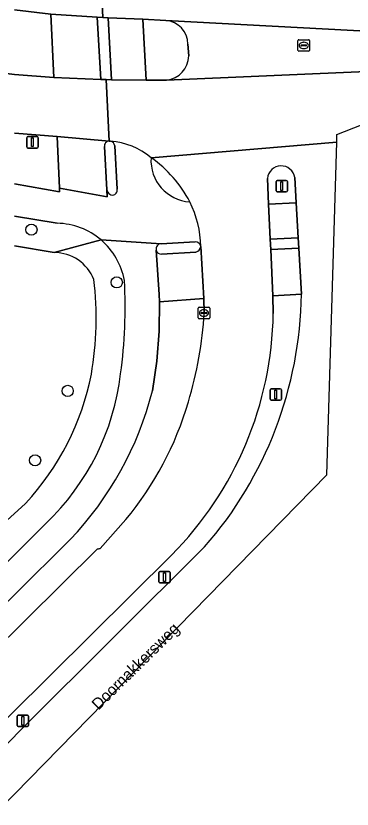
# Model space of a CAD drawing. Extents: x 162989 to 165008, y 383432 to 384338.
# Drawn here: x 164500.1 to 164529.5, y 383437.3 to 383506.5 of the extents above; entities that cross this region are included whole.
import ezdxf

# ---------------------------------------------------------------- set-up
doc = ezdxf.new("R2010")
doc.units = 0
for name, color, linetype in [('IMGEO_Boom', 7, 'Continuous'), ('IMGEO_Fietspad_open', 7, 'Continuous'), ('IMGEO_Groenvoorziening', 7, 'Continuous'), ('IMGEO_Kolk', 7, 'Continuous'), ('IMGEO_Lichtmast', 7, 'Continuous'), ('IMGEO_Openbare_ruimte_label', 7, 'Continuous'), ('IMGEO_Rijbaan_lokaal_open', 7, 'Continuous'), ('IMGEO_Rioolput', 7, 'Continuous'), ('IMGEO_Verkeerseiland_open', 7, 'Continuous'), ('IMGEO_Voetpad_open', 7, 'Continuous')]:
    doc.layers.add(name, color=color, linetype=linetype)

msp = doc.modelspace()

# ---------------------------------------------------------------- linework, layer by layer
at = {"layer": 'IMGEO_Boom'}
for centre in [(164501.471, 383487.838), (164508.917, 383483.242), (164504.637, 383473.78), (164501.79, 383467.725)]:
    msp.add_circle(centre, 0.489, dxfattribs=at)
at = {"layer": 'IMGEO_Fietspad_open'}
for points in [[(164508.175, 383506.302), (164508.462, 383500.91), (164511.494, 383500.886), (164511.191, 383506.197)], [(164522.169, 383490.055), (164522.306, 383487.021), (164524.749, 383487.13), (164524.575, 383490.167)]]:
    msp.add_lwpolyline(points, close=True, dxfattribs=at)
for points in [[(164508.736, 383495.164), (164508.961, 383491.369)], [(164508.065, 383491.313), (164508.078, 383490.705), (164503.931, 383491.447), (164503.925, 383491.144), (164500, 383491.824)], [(164500, 383489.02), (164503.729, 383488.399)], [(164512.789, 383486.617), (164507.545, 383486.942)], [(164507.545, 383486.942), (164512.789, 383486.617), (164515.771, 383486.781)], [(164512.027, 383473.783), (164512.425, 383476.376), (164512.63, 383478.992), (164512.642, 383481.539), (164512.604, 383482.199), (164512.352, 383486.065)], [(164502.742, 383462.221), (164500, 383459.479), (164492.313, 383451.968), (164487.834, 383447.544), (164489.625, 383445.869), (164491.555, 383447.775), (164494.035, 383450.225), (164500, 383456.001), (164504.839, 383460.807)]]:
    msp.add_lwpolyline(points, dxfattribs=at)
for centre, radius, start, end in [((164507.881, 383489.285), 6.288, 50.18021, 85.4974), ((164508.288, 383495.112), 0.451, 6.65512, 78.92211), ((164515.54, 383493.888), 3.639, 176.427, 266.03104), ((164508.567, 383491.361), 0.504, 185.47352, 270.70178), ((164508.522, 383491.299), 0.445, 276.64521, 9.04418), ((164507.422, 383486.258), 8.824, 0.75448, 26.95674), ((164503.585, 383482.297), 6.104, 49.55365, 88.6513), ((164503.587, 383482.299), 6.101, 10.44461, 49.55325), ((164512.824, 383486.141), 0.478, 94.14439, 189.12064), ((164515.78, 383486.311), 0.47, 7.6989, 91.11839), ((164466.759, 383481.075), 42.891, 352.23468, 3.11369), ((164487.794, 383477.833), 21.614, 313.75529, 353.21644), ((164483.733, 383480.977), 29.194, 316.29812, 345.73373)]:
    msp.add_arc(centre, radius, start, end, dxfattribs=at)
at = {"layer": 'IMGEO_Groenvoorziening'}
for points in [[(164500, 383491.824), (164503.925, 383491.144), (164503.931, 383491.447), (164503.705, 383495.962), (164500, 383496.248)], [(164477.652, 383492.496), (164481.464, 383487.201), (164486.535, 383481.42), (164488.702, 383478.589), (164492.282, 383473.121), (164497.415, 383463.608), (164498.327, 383461.598), (164500.966, 383463.964)], [(164503.462, 383485.847), (164500, 383486.434)], [(164516.552, 383480.597), (164516.501, 383481.85), (164512.642, 383481.539), (164512.63, 383478.992), (164512.425, 383476.376), (164512.027, 383473.783)], [(164504.839, 383460.807), (164500, 383456.001), (164494.035, 383450.225), (164491.555, 383447.775), (164493.231, 383446.235), (164493.418, 383446.419), (164494.784, 383447.72), (164507.212, 383459.964), (164507.457, 383460.024), (164509.711, 383462.56)]]:
    msp.add_lwpolyline(points, dxfattribs=at)
for centre, radius, start, end in [((164503.432, 383482.083), 3.764, 22.02729, 89.54402), ((164478.075, 383480.132), 29.041, 350.28617, 6.64972), ((164482.063, 383482.734), 34.555, 343.31323, 356.45424), ((164483.929, 383479.727), 23.21, 317.22478, 348.83444), ((164483.733, 383480.977), 29.194, 316.29812, 345.73373), ((164487.576, 383480.907), 28.751, 320.34588, 343.64614)]:
    msp.add_arc(centre, radius, start, end, dxfattribs=at)
at = {"layer": 'IMGEO_Kolk'}
for p, q in [((164516.024, 383480.149), (164516.024, 383481.001)), ((164516.099, 383481.075), (164516.951, 383481.075)), ((164516.512, 383480.855), (164516.537, 383480.855)), ((164517.025, 383481.001), (164517.025, 383480.149)), ((164516.951, 383480.075), (164516.099, 383480.075)), ((164516.283, 383480.569), (164516.283, 383480.581)), ((164516.721, 383480.532), (164516.323, 383480.532)), ((164516.326, 383480.618), (164516.724, 383480.618)), ((164516.535, 383480.295), (164516.51, 383480.295)), ((164516.767, 383480.581), (164516.767, 383480.569))]:
    msp.add_line(p, q, dxfattribs=at)
for points in [[(164516.024, 383480.149), (164516.024, 383481.001)], [(164516.099, 383481.075), (164516.951, 383481.075)], [(164517.025, 383481.001), (164517.025, 383480.149)], [(164516.951, 383480.075), (164516.099, 383480.075)]]:
    msp.add_lwpolyline(points, dxfattribs=at)
for centre, radius, start, end in [((164516.101, 383480.999), 0.0765, 91.55205, 178.44795), ((164516.101, 383480.999), 0.0765, 91.55205, 178.44795), ((164516.949, 383480.999), 0.0765, 1.55205, 88.44795), ((164516.949, 383480.999), 0.0765, 1.55205, 88.44795), ((164516.101, 383480.151), 0.0765, 181.55205, 268.44795), ((164516.101, 383480.151), 0.0765, 181.55205, 268.44795), ((164516.323, 383480.578), 0.0403, 85.87752, 175.75265), ((164516.32, 383480.568), 0.0366, 178.93798, 274.71019), ((164516.724, 383480.575), 0.043, 264.86636, 352.45326), ((164516.728, 383480.58), 0.0386, 1.73085, 96.63898), ((164516.949, 383480.151), 0.0765, 271.55205, 358.44795), ((164516.949, 383480.151), 0.0765, 271.55205, 358.44795)]:
    msp.add_arc(centre, radius, start, end, dxfattribs=at)
for centre, major_axis, ratio, start_param, end_param in [((164516.511, 383480.575), (-0.387, 0.002), 0.722429, 4.712389, 7.853982), ((164516.536, 383480.575), (-0.39, 0.002), 0.717154, 1.570796, 4.712389)]:
    msp.add_ellipse(centre, major_axis=major_axis, ratio=ratio, start_param=start_param, end_param=end_param, dxfattribs=at)
at = {"layer": 'IMGEO_Lichtmast'}
for p, q in [((164501.161, 383495.959), (164501.951, 383495.959)), ((164501.951, 383495.959), (164501.161, 383495.959)), ((164501.061, 383495.059), (164501.061, 383495.859)), ((164501.061, 383495.859), (164501.061, 383495.059)), ((164502.051, 383495.859), (164502.051, 383495.059)), ((164502.051, 383495.059), (164502.051, 383495.859)), ((164501.951, 383494.959), (164501.161, 383494.959)), ((164501.161, 383494.959), (164501.951, 383494.959)), ((164522.82, 383491.233), (164522.82, 383492.033)), ((164522.82, 383492.033), (164522.82, 383491.233)), ((164522.92, 383492.133), (164523.71, 383492.133)), ((164523.71, 383492.133), (164522.92, 383492.133)), ((164523.81, 383492.033), (164523.81, 383491.233)), ((164523.81, 383491.233), (164523.81, 383492.033)), ((164523.71, 383491.133), (164522.92, 383491.133)), ((164522.92, 383491.133), (164523.71, 383491.133)), ((164522.299, 383473.06), (164522.299, 383473.86)), ((164522.299, 383473.86), (164522.299, 383473.06)), ((164522.399, 383473.96), (164523.189, 383473.96)), ((164523.189, 383473.96), (164522.399, 383473.96)), ((164523.289, 383473.86), (164523.289, 383473.06)), ((164523.289, 383473.06), (164523.289, 383473.86)), ((164523.189, 383472.96), (164522.399, 383472.96)), ((164522.399, 383472.96), (164523.189, 383472.96)), ((164512.588, 383457.129), (164512.588, 383457.929)), ((164512.588, 383457.929), (164512.588, 383457.129)), ((164512.688, 383458.029), (164513.478, 383458.029)), ((164513.478, 383458.029), (164512.688, 383458.029)), ((164513.578, 383457.929), (164513.578, 383457.129)), ((164513.578, 383457.129), (164513.578, 383457.929)), ((164513.478, 383457.029), (164512.688, 383457.029)), ((164512.688, 383457.029), (164513.478, 383457.029)), ((164500.225, 383444.609), (164500.225, 383445.409)), ((164500.225, 383445.409), (164500.225, 383444.609)), ((164500.325, 383445.509), (164501.115, 383445.509)), ((164501.115, 383445.509), (164500.325, 383445.509)), ((164501.215, 383445.409), (164501.215, 383444.609)), ((164501.215, 383444.609), (164501.215, 383445.409)), ((164501.115, 383444.509), (164500.325, 383444.509)), ((164500.325, 383444.509), (164501.115, 383444.509))]:
    msp.add_line(p, q, dxfattribs=at)
for points in [[(164501.481, 383495.834), (164501.631, 383495.834), (164501.631, 383495.084), (164501.481, 383495.084), (164501.481, 383495.834)], [(164523.24, 383492.008), (164523.39, 383492.008), (164523.39, 383491.258), (164523.24, 383491.258), (164523.24, 383492.008)], [(164522.719, 383473.835), (164522.869, 383473.835), (164522.869, 383473.085), (164522.719, 383473.085), (164522.719, 383473.835)], [(164513.008, 383457.904), (164513.158, 383457.904), (164513.158, 383457.154), (164513.008, 383457.154), (164513.008, 383457.904)], [(164500.645, 383445.384), (164500.795, 383445.384), (164500.795, 383444.634), (164500.645, 383444.634), (164500.645, 383445.384)]]:
    msp.add_lwpolyline(points, dxfattribs=at)
for centre, start, end in [((164501.161, 383495.859), 90, 180), ((164501.161, 383495.859), 90, 180), ((164501.951, 383495.859), 0, 90), ((164501.951, 383495.859), 360, 90), ((164501.161, 383495.059), 180, 270), ((164501.161, 383495.059), 180, 270), ((164501.951, 383495.059), 270, 0), ((164501.951, 383495.059), 270, 0), ((164522.92, 383492.033), 90, 180), ((164522.92, 383492.033), 90, 180), ((164523.71, 383492.033), 0, 90), ((164523.71, 383492.033), 360, 90), ((164522.92, 383491.233), 180, 270), ((164522.92, 383491.233), 180, 270), ((164523.71, 383491.233), 270, 0), ((164523.71, 383491.233), 270, 0), ((164522.399, 383473.86), 90, 180), ((164522.399, 383473.86), 90, 180), ((164523.189, 383473.86), 0, 90), ((164523.189, 383473.86), 360, 90), ((164522.399, 383473.06), 180, 270), ((164522.399, 383473.06), 180, 270), ((164523.189, 383473.06), 270, 0), ((164523.189, 383473.06), 270, 0), ((164512.688, 383457.929), 90, 180), ((164512.688, 383457.929), 90, 180), ((164513.478, 383457.929), 0, 90), ((164513.478, 383457.929), 360, 90), ((164512.688, 383457.129), 180, 270), ((164512.688, 383457.129), 180, 270), ((164513.478, 383457.129), 270, 0), ((164513.478, 383457.129), 270, 0), ((164500.325, 383445.409), 90, 180), ((164500.325, 383445.409), 90, 180), ((164501.115, 383445.409), 0, 90), ((164501.115, 383445.409), 360, 90), ((164500.325, 383444.609), 180, 270), ((164500.325, 383444.609), 180, 270), ((164501.115, 383444.609), 270, 0), ((164501.115, 383444.609), 270, 0)]:
    msp.add_arc(centre, 0.1, start, end, dxfattribs=at)
at = {"layer": 'IMGEO_Rijbaan_lokaal_open'}
msp.add_lwpolyline([(164542.712, 383514.34), (164538.543, 383513.538), (164537.638, 383513.363), (164534.668, 383512.79), (164528.38, 383511.934), (164522.119, 383511.413), (164516.289, 383511.213), (164514.847, 383511.214), (164510.885, 383511.312), (164507.475, 383511.395), (164507.697, 383506.333), (164508.175, 383506.302), (164511.191, 383506.197), (164513.186, 383506.086), (164531.761, 383505.078), (164534.995, 383505.6), (164538.051, 383506.113), (164538.944, 383506.259), (164542.938, 383507.087)], close=True, dxfattribs=at)
for points in [[(164500, 383507.002), (164503.167, 383506.638), (164507.219, 383506.364), (164507.697, 383506.333), (164507.475, 383511.395), (164507.076, 383511.421), (164502.838, 383511.721), (164500.502, 383511.982), (164500, 383512.049)], [(164531.761, 383505.078), (164513.186, 383506.086)], [(164528.111, 383495.461), (164528.131, 383496.148), (164543.193, 383502.048), (164543.059, 383504.348), (164539.112, 383503.172), (164538.185, 383502.929), (164535.175, 383502.19), (164532.146, 383501.447)], [(164515.13, 383504.021), (164515.197, 383502.995)], [(164500, 383496.248), (164503.705, 383495.962), (164508.259, 383495.562), (164507.99, 383500.92), (164507.518, 383500.931), (164503.413, 383501.109), (164500, 383501.377), (164497.613, 383501.662)], [(164531.372, 383501.656), (164513.263, 383500.884), (164511.494, 383500.886), (164508.462, 383500.91), (164507.99, 383500.92), (164508.259, 383495.562), (164508.317, 383495.562), (164508.375, 383495.554)], [(164513.263, 383500.884), (164531.372, 383501.656)], [(164498.674, 383437.308), (164527.247, 383466.465), (164528.111, 383495.461), (164511.908, 383494.115)], [(164511.908, 383494.115), (164528.111, 383495.461)], [(164522.575, 383480.541), (164522.527, 383482.062), (164522.347, 383486.109), (164522.306, 383487.021), (164522.169, 383490.055), (164522.068, 383492.313)], [(164524.448, 383492.389), (164524.575, 383490.167), (164524.749, 383487.13), (164524.801, 383486.224), (164525.029, 383482.208)], [(164516.246, 383486.374), (164516.501, 383481.85), (164516.552, 383480.597)], [(164509.711, 383462.56), (164507.457, 383460.024), (164507.212, 383459.964), (164494.784, 383447.72), (164493.418, 383446.419), (164493.231, 383446.235), (164491.282, 383444.315), (164495.278, 383440.501), (164496.648, 383439.243), (164498.674, 383437.308)], [(164516.586, 383460.179), (164500.761, 383444.422), (164497.91, 383441.55), (164497.196, 383440.873), (164497.017, 383440.747), (164496.792, 383440.675), (164496.551, 383440.678), (164496.328, 383440.755), (164496.152, 383440.885), (164496.136, 383440.9), (164496.005, 383441.075), (164495.927, 383441.298), (164495.922, 383441.539), (164495.992, 383441.764), (164496.117, 383441.944), (164496.789, 383442.663), (164499.64, 383445.535), (164513.695, 383459.464)]]:
    msp.add_lwpolyline(points, dxfattribs=at)
for centre, radius, start, end in [((164513.041, 383504.002), 2.089, 0.52377, 86.01866), ((164513.042, 383503.028), 2.156, 275.8947, 359.11636), ((164507.881, 383489.285), 6.288, 50.18021, 85.4974), ((164505.848, 383485.395), 10.619, 27.25535, 55.20269), ((164523.263, 383492.202), 1.2, 8.98084, 174.67714), ((164507.422, 383486.258), 8.824, 0.75448, 26.95674), ((164490.881, 383482.663), 34.151, 318.82343, 359.23616), ((164492.003, 383481.012), 30.576, 315.19045, 359.11696), ((164482.063, 383482.734), 34.555, 343.31323, 356.45424), ((164487.576, 383480.907), 28.751, 320.34588, 343.64614)]:
    msp.add_arc(centre, radius, start, end, dxfattribs=at)
at = {"layer": 'IMGEO_Rioolput'}
for p, q in [((164524.731, 383503.477), (164524.731, 383504.329)), ((164524.806, 383504.403), (164525.658, 383504.403)), ((164525.732, 383504.329), (164525.732, 383503.477)), ((164524.99, 383503.897), (164524.99, 383503.909)), ((164525.428, 383503.86), (164525.03, 383503.86)), ((164525.033, 383503.946), (164525.431, 383503.946)), ((164525.242, 383503.623), (164525.217, 383503.623)), ((164525.219, 383504.183), (164525.244, 383504.183)), ((164525.474, 383503.909), (164525.474, 383503.897)), ((164525.658, 383503.403), (164524.806, 383503.403))]:
    msp.add_line(p, q, dxfattribs=at)
for points in [[(164524.731, 383503.477), (164524.731, 383504.329)], [(164524.806, 383504.403), (164525.658, 383504.403)], [(164525.732, 383504.329), (164525.732, 383503.477)], [(164525.658, 383503.403), (164524.806, 383503.403)]]:
    msp.add_lwpolyline(points, dxfattribs=at)
for centre, radius, start, end in [((164524.808, 383504.327), 0.0765, 91.55205, 178.44795), ((164524.808, 383504.327), 0.0765, 91.55205, 178.44795), ((164525.656, 383504.327), 0.0765, 1.55205, 88.44795), ((164525.656, 383504.327), 0.0765, 1.55205, 88.44795), ((164525.03, 383503.906), 0.0403, 85.87752, 175.75265), ((164525.027, 383503.896), 0.0366, 178.93798, 274.71019), ((164525.431, 383503.903), 0.043, 264.86636, 352.45326), ((164525.435, 383503.908), 0.0386, 1.73085, 96.63898), ((164524.808, 383503.479), 0.0765, 181.55205, 268.44795), ((164524.808, 383503.479), 0.0765, 181.55205, 268.44795), ((164525.656, 383503.479), 0.0765, 271.55205, 358.44795), ((164525.656, 383503.479), 0.0765, 271.55205, 358.44795)]:
    msp.add_arc(centre, radius, start, end, dxfattribs=at)
for centre, major_axis, ratio, start_param, end_param in [((164525.218, 383503.903), (-0.387, 0.002), 0.722429, 4.712389, 7.853982), ((164525.243, 383503.903), (-0.39, 0.002), 0.717154, 1.570796, 4.712389)]:
    msp.add_ellipse(centre, major_axis=major_axis, ratio=ratio, start_param=start_param, end_param=end_param, dxfattribs=at)
at = {"layer": 'IMGEO_Verkeerseiland_open'}
for points in [[(164497.613, 383501.662), (164500, 383501.377), (164503.413, 383501.109), (164503.167, 383506.638), (164500, 383507.002)], [(164513.186, 383506.086), (164511.191, 383506.197), (164511.494, 383500.886), (164513.263, 383500.884)], [(164515.197, 383502.995), (164515.13, 383504.021)], [(164508.375, 383495.554), (164508.317, 383495.562), (164508.259, 383495.562)], [(164507.841, 383495.093), (164508.065, 383491.313)], [(164508.961, 383491.369), (164508.736, 383495.164)], [(164522.068, 383492.313), (164522.169, 383490.055), (164524.575, 383490.167), (164524.448, 383492.389)], [(164515.771, 383486.781), (164512.789, 383486.617)], [(164512.825, 383485.708), (164515.821, 383485.888)], [(164525.029, 383482.208), (164522.527, 383482.062), (164522.575, 383480.541)], [(164513.695, 383459.464), (164499.64, 383445.535), (164496.789, 383442.663), (164496.117, 383441.944), (164495.992, 383441.764), (164495.922, 383441.539), (164495.927, 383441.298), (164496.005, 383441.075), (164496.136, 383440.9), (164496.152, 383440.885), (164496.328, 383440.755), (164496.551, 383440.678), (164496.792, 383440.675), (164497.017, 383440.747), (164497.196, 383440.873), (164497.91, 383441.55), (164500.761, 383444.422), (164516.586, 383460.179)]]:
    msp.add_lwpolyline(points, dxfattribs=at)
for points in [[(164508.175, 383506.302), (164507.697, 383506.333), (164507.219, 383506.364), (164507.518, 383500.931), (164507.99, 383500.92), (164508.462, 383500.91)], [(164524.801, 383486.224), (164524.749, 383487.13), (164522.306, 383487.021), (164522.347, 383486.109)]]:
    msp.add_lwpolyline(points, close=True, dxfattribs=at)
for centre, radius, start, end in [((164513.041, 383504.002), 2.089, 0.52377, 86.01866), ((164513.042, 383503.028), 2.156, 275.8947, 359.11636), ((164508.268, 383495.134), 0.429, 91.15494, 185.4265), ((164508.288, 383495.112), 0.451, 6.65512, 78.92211), ((164515.54, 383493.888), 3.639, 176.427, 266.03104), ((164505.848, 383485.395), 10.619, 27.25535, 55.20269), ((164523.263, 383492.202), 1.2, 8.98084, 174.67714), ((164508.567, 383491.361), 0.504, 185.47352, 270.70178), ((164508.522, 383491.299), 0.445, 276.64521, 9.04418), ((164512.824, 383486.141), 0.478, 94.14439, 189.12064), ((164515.78, 383486.311), 0.47, 7.6989, 91.11839), ((164515.708, 383486.415), 0.539, 282.04603, 355.61551), ((164512.803, 383486.171), 0.463, 193.21051, 272.70163), ((164490.881, 383482.663), 34.151, 318.82343, 359.23616), ((164492.003, 383481.012), 30.576, 315.19045, 359.11696)]:
    msp.add_arc(centre, radius, start, end, dxfattribs=at)
at = {"layer": 'IMGEO_Voetpad_open'}
for points in [[(164503.167, 383506.638), (164503.413, 383501.109), (164507.518, 383500.931), (164507.219, 383506.364)], [(164524.801, 383486.224), (164522.347, 383486.109), (164522.527, 383482.062), (164525.029, 383482.208)]]:
    msp.add_lwpolyline(points, close=True, dxfattribs=at)
for points in [[(164508.259, 383495.562), (164503.705, 383495.962), (164503.931, 383491.447), (164508.078, 383490.705), (164508.065, 383491.313), (164507.841, 383495.093)], [(164503.729, 383488.399), (164500, 383489.02)], [(164500, 383486.434), (164503.462, 383485.847), (164507.545, 383486.942)], [(164507.545, 383486.942), (164503.462, 383485.847)], [(164512.352, 383486.065), (164512.604, 383482.199), (164512.642, 383481.539), (164516.501, 383481.85), (164516.246, 383486.374)], [(164515.821, 383485.888), (164512.825, 383485.708)], [(164500.966, 383463.964), (164498.327, 383461.598), (164496.487, 383459.754), (164488.83, 383452.266), (164488.725, 383452.374), (164487.652, 383451.325), (164487.757, 383451.218), (164487.581, 383451.045), (164485.862, 383449.388), (164487.834, 383447.544), (164492.313, 383451.968), (164500, 383459.479), (164502.742, 383462.221)]]:
    msp.add_lwpolyline(points, dxfattribs=at)
for centre, radius, start, end in [((164508.268, 383495.134), 0.429, 91.15494, 185.4265), ((164503.585, 383482.297), 6.104, 49.55365, 88.6513), ((164503.587, 383482.299), 6.101, 10.44461, 49.55325), ((164515.708, 383486.415), 0.539, 282.04603, 355.61551), ((164503.432, 383482.083), 3.764, 22.02729, 89.54402), ((164512.803, 383486.171), 0.463, 193.21051, 272.70163), ((164478.075, 383480.132), 29.041, 350.28617, 6.64972), ((164466.759, 383481.075), 42.891, 352.23468, 3.11369), ((164483.929, 383479.727), 23.21, 317.22478, 348.83444), ((164487.794, 383477.833), 21.614, 313.75529, 353.21644)]:
    msp.add_arc(centre, radius, start, end, dxfattribs=at)

# ---------------------------------------------------------------- texts
at = {"layer": 'IMGEO_Openbare_ruimte_label'}
msp.add_text('Doornakkersweg', height=1, rotation=44.5948, dxfattribs=at).set_placement((164507.323, 383445.89))

doc.saveas('drawing.dxf')
